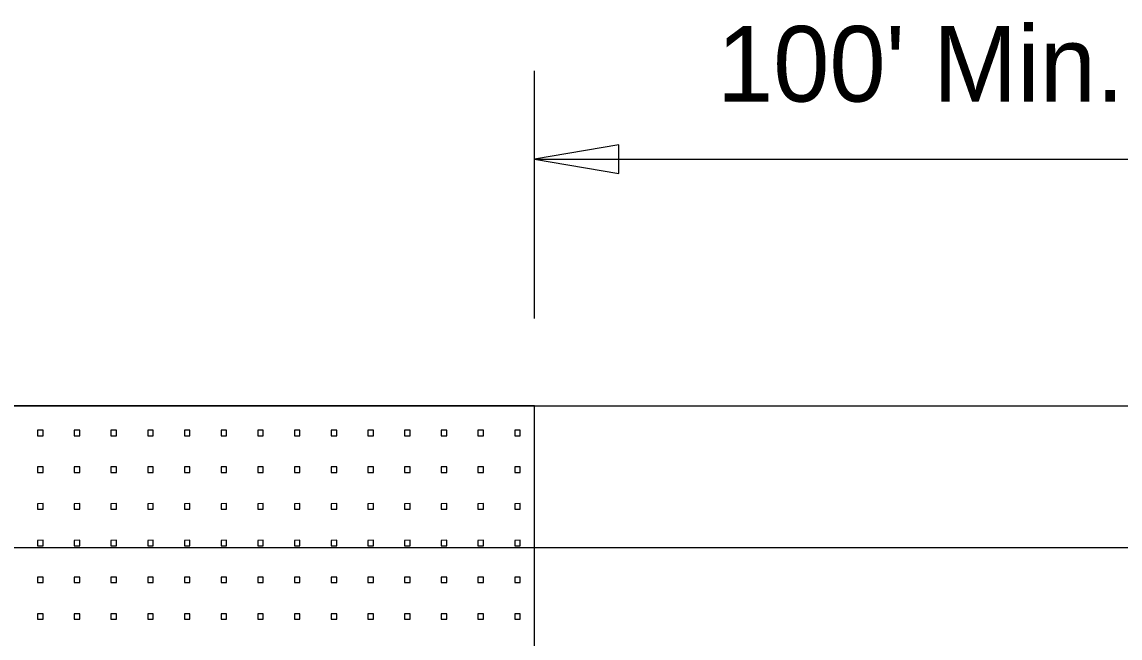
# Model space of a CAD drawing. Extents: x 10000 to 10825, y 10000 to 10530.
# Drawn here: x 10231.1 to 10281.9, y 10433.5 to 10462 of the extents above; entities that cross this region are included whole.
import ezdxf

# ---------------------------------------------------------------- set-up
doc = ezdxf.new("R2010")
doc.units = 0
for name, color, linetype in [('Default', 7, 'Continuous'), ('Dimension', 7, 'Continuous'), ('TextStructures', 7, 'Continuous')]:
    doc.layers.add(name, color=color, linetype=linetype)

msp = doc.modelspace()

# ---------------------------------------------------------------- linework, layer by layer
at = {"layer": 'Default'}
for p, q in [((10254.769, 10448.295), (10254.769, 10459.771)), ((10254.769, 10455.673), (10290.826, 10455.673)), ((10049.563, 10444.263), (10394.364, 10444.263)), ((10254.769, 10444.263), (10187.058, 10444.263)), ((10254.769, 10404.79), (10254.769, 10444.263)), ((10049.563, 10437.701), (10394.364, 10437.701))]:
    msp.add_line(p, q, dxfattribs=at)
for points in [[(10232.033, 10442.872), (10232.033, 10443.128), (10231.778, 10443.127), (10231.778, 10442.872), (10232.033, 10442.872)], [(10232.033, 10442.872), (10232.033, 10443.128), (10231.778, 10443.127), (10231.778, 10442.872), (10232.033, 10442.872)], [(10233.732, 10442.872), (10233.732, 10443.128), (10233.477, 10443.127), (10233.477, 10442.872), (10233.732, 10442.872)], [(10233.732, 10442.872), (10233.732, 10443.128), (10233.477, 10443.127), (10233.477, 10442.872), (10233.732, 10442.872)], [(10235.43, 10442.872), (10235.43, 10443.128), (10235.175, 10443.127), (10235.175, 10442.872), (10235.43, 10442.872)], [(10235.43, 10442.872), (10235.43, 10443.128), (10235.175, 10443.127), (10235.175, 10442.872), (10235.43, 10442.872)], [(10237.128, 10442.872), (10237.128, 10443.128), (10236.874, 10443.127), (10236.874, 10442.872), (10237.128, 10442.872)], [(10237.128, 10442.872), (10237.128, 10443.128), (10236.874, 10443.127), (10236.874, 10442.872), (10237.128, 10442.872)], [(10238.827, 10442.872), (10238.827, 10443.128), (10238.572, 10443.127), (10238.572, 10442.872), (10238.827, 10442.872)], [(10238.827, 10442.872), (10238.827, 10443.128), (10238.572, 10443.127), (10238.572, 10442.872), (10238.827, 10442.872)], [(10240.525, 10442.872), (10240.525, 10443.128), (10240.271, 10443.127), (10240.271, 10442.872), (10240.525, 10442.872)], [(10240.525, 10442.872), (10240.525, 10443.128), (10240.271, 10443.127), (10240.271, 10442.872), (10240.525, 10442.872)], [(10242.224, 10442.872), (10242.224, 10443.128), (10241.969, 10443.127), (10241.969, 10442.872), (10242.224, 10442.872)], [(10242.224, 10442.872), (10242.224, 10443.128), (10241.969, 10443.127), (10241.969, 10442.872), (10242.224, 10442.872)], [(10243.922, 10442.872), (10243.922, 10443.128), (10243.668, 10443.127), (10243.668, 10442.872), (10243.922, 10442.872)], [(10243.922, 10442.872), (10243.922, 10443.128), (10243.668, 10443.127), (10243.668, 10442.872), (10243.922, 10442.872)], [(10245.621, 10442.872), (10245.621, 10443.128), (10245.366, 10443.127), (10245.366, 10442.872), (10245.621, 10442.872)], [(10245.621, 10442.872), (10245.621, 10443.128), (10245.366, 10443.127), (10245.366, 10442.872), (10245.621, 10442.872)], [(10247.319, 10442.872), (10247.319, 10443.128), (10247.065, 10443.127), (10247.065, 10442.872), (10247.319, 10442.872)], [(10247.319, 10442.872), (10247.319, 10443.128), (10247.065, 10443.127), (10247.065, 10442.872), (10247.319, 10442.872)], [(10249.018, 10442.872), (10249.018, 10443.128), (10248.763, 10443.127), (10248.763, 10442.872), (10249.018, 10442.872)], [(10249.018, 10442.872), (10249.018, 10443.128), (10248.763, 10443.127), (10248.763, 10442.872), (10249.018, 10442.872)], [(10250.716, 10442.872), (10250.716, 10443.128), (10250.462, 10443.127), (10250.462, 10442.872), (10250.716, 10442.872)], [(10250.716, 10442.872), (10250.716, 10443.128), (10250.462, 10443.127), (10250.462, 10442.872), (10250.716, 10442.872)], [(10252.415, 10442.872), (10252.415, 10443.128), (10252.16, 10443.127), (10252.16, 10442.872), (10252.415, 10442.872)], [(10252.415, 10442.872), (10252.415, 10443.128), (10252.16, 10443.127), (10252.16, 10442.872), (10252.415, 10442.872)], [(10254.113, 10442.872), (10254.113, 10443.128), (10253.858, 10443.127), (10253.858, 10442.872), (10254.113, 10442.872)], [(10254.113, 10442.872), (10254.113, 10443.128), (10253.858, 10443.127), (10253.858, 10442.872), (10254.113, 10442.872)], [(10232.033, 10441.174), (10232.033, 10441.43), (10231.778, 10441.429), (10231.778, 10441.174), (10232.033, 10441.174)], [(10232.033, 10441.174), (10232.033, 10441.43), (10231.778, 10441.429), (10231.778, 10441.174), (10232.033, 10441.174)], [(10233.732, 10441.174), (10233.732, 10441.43), (10233.477, 10441.429), (10233.477, 10441.174), (10233.732, 10441.174)], [(10233.732, 10441.174), (10233.732, 10441.43), (10233.477, 10441.429), (10233.477, 10441.174), (10233.732, 10441.174)], [(10235.43, 10441.174), (10235.43, 10441.43), (10235.175, 10441.429), (10235.175, 10441.174), (10235.43, 10441.174)], [(10235.43, 10441.174), (10235.43, 10441.43), (10235.175, 10441.429), (10235.175, 10441.174), (10235.43, 10441.174)], [(10237.128, 10441.174), (10237.128, 10441.43), (10236.874, 10441.429), (10236.874, 10441.174), (10237.128, 10441.174)], [(10237.128, 10441.174), (10237.128, 10441.43), (10236.874, 10441.429), (10236.874, 10441.174), (10237.128, 10441.174)], [(10238.827, 10441.174), (10238.827, 10441.43), (10238.572, 10441.429), (10238.572, 10441.174), (10238.827, 10441.174)], [(10238.827, 10441.174), (10238.827, 10441.43), (10238.572, 10441.429), (10238.572, 10441.174), (10238.827, 10441.174)], [(10240.525, 10441.174), (10240.525, 10441.43), (10240.271, 10441.429), (10240.271, 10441.174), (10240.525, 10441.174)], [(10240.525, 10441.174), (10240.525, 10441.43), (10240.271, 10441.429), (10240.271, 10441.174), (10240.525, 10441.174)], [(10242.224, 10441.174), (10242.224, 10441.43), (10241.969, 10441.429), (10241.969, 10441.174), (10242.224, 10441.174)], [(10242.224, 10441.174), (10242.224, 10441.43), (10241.969, 10441.429), (10241.969, 10441.174), (10242.224, 10441.174)], [(10243.922, 10441.174), (10243.922, 10441.43), (10243.668, 10441.429), (10243.668, 10441.174), (10243.922, 10441.174)], [(10243.922, 10441.174), (10243.922, 10441.43), (10243.668, 10441.429), (10243.668, 10441.174), (10243.922, 10441.174)], [(10245.621, 10441.174), (10245.621, 10441.43), (10245.366, 10441.429), (10245.366, 10441.174), (10245.621, 10441.174)], [(10245.621, 10441.174), (10245.621, 10441.43), (10245.366, 10441.429), (10245.366, 10441.174), (10245.621, 10441.174)], [(10247.319, 10441.174), (10247.319, 10441.43), (10247.065, 10441.429), (10247.065, 10441.174), (10247.319, 10441.174)], [(10247.319, 10441.174), (10247.319, 10441.43), (10247.065, 10441.429), (10247.065, 10441.174), (10247.319, 10441.174)], [(10249.018, 10441.174), (10249.018, 10441.43), (10248.763, 10441.429), (10248.763, 10441.174), (10249.018, 10441.174)], [(10249.018, 10441.174), (10249.018, 10441.43), (10248.763, 10441.429), (10248.763, 10441.174), (10249.018, 10441.174)], [(10250.716, 10441.174), (10250.716, 10441.43), (10250.462, 10441.429), (10250.462, 10441.174), (10250.716, 10441.174)], [(10250.716, 10441.174), (10250.716, 10441.43), (10250.462, 10441.429), (10250.462, 10441.174), (10250.716, 10441.174)], [(10252.415, 10441.174), (10252.415, 10441.43), (10252.16, 10441.429), (10252.16, 10441.174), (10252.415, 10441.174)], [(10252.415, 10441.174), (10252.415, 10441.43), (10252.16, 10441.429), (10252.16, 10441.174), (10252.415, 10441.174)], [(10254.113, 10441.174), (10254.113, 10441.43), (10253.858, 10441.429), (10253.858, 10441.174), (10254.113, 10441.174)], [(10254.113, 10441.174), (10254.113, 10441.43), (10253.858, 10441.429), (10253.858, 10441.174), (10254.113, 10441.174)], [(10232.033, 10439.475), (10232.033, 10439.731), (10231.778, 10439.73), (10231.778, 10439.475), (10232.033, 10439.475)], [(10232.033, 10439.475), (10232.033, 10439.731), (10231.778, 10439.73), (10231.778, 10439.475), (10232.033, 10439.475)], [(10233.732, 10439.475), (10233.732, 10439.731), (10233.477, 10439.73), (10233.477, 10439.475), (10233.732, 10439.475)], [(10233.732, 10439.475), (10233.732, 10439.731), (10233.477, 10439.73), (10233.477, 10439.475), (10233.732, 10439.475)], [(10235.43, 10439.475), (10235.43, 10439.731), (10235.175, 10439.73), (10235.175, 10439.475), (10235.43, 10439.475)], [(10235.43, 10439.475), (10235.43, 10439.731), (10235.175, 10439.73), (10235.175, 10439.475), (10235.43, 10439.475)], [(10237.128, 10439.475), (10237.128, 10439.731), (10236.874, 10439.73), (10236.874, 10439.475), (10237.128, 10439.475)], [(10237.128, 10439.475), (10237.128, 10439.731), (10236.874, 10439.73), (10236.874, 10439.475), (10237.128, 10439.475)], [(10238.827, 10439.475), (10238.827, 10439.731), (10238.572, 10439.73), (10238.572, 10439.475), (10238.827, 10439.475)], [(10238.827, 10439.475), (10238.827, 10439.731), (10238.572, 10439.73), (10238.572, 10439.475), (10238.827, 10439.475)], [(10240.525, 10439.475), (10240.525, 10439.731), (10240.271, 10439.73), (10240.271, 10439.475), (10240.525, 10439.475)], [(10240.525, 10439.475), (10240.525, 10439.731), (10240.271, 10439.73), (10240.271, 10439.475), (10240.525, 10439.475)], [(10242.224, 10439.475), (10242.224, 10439.731), (10241.969, 10439.73), (10241.969, 10439.475), (10242.224, 10439.475)], [(10242.224, 10439.475), (10242.224, 10439.731), (10241.969, 10439.73), (10241.969, 10439.475), (10242.224, 10439.475)], [(10243.922, 10439.475), (10243.922, 10439.731), (10243.668, 10439.73), (10243.668, 10439.475), (10243.922, 10439.475)], [(10243.922, 10439.475), (10243.922, 10439.731), (10243.668, 10439.73), (10243.668, 10439.475), (10243.922, 10439.475)], [(10245.621, 10439.475), (10245.621, 10439.731), (10245.366, 10439.73), (10245.366, 10439.475), (10245.621, 10439.475)], [(10245.621, 10439.475), (10245.621, 10439.731), (10245.366, 10439.73), (10245.366, 10439.475), (10245.621, 10439.475)], [(10247.319, 10439.475), (10247.319, 10439.731), (10247.065, 10439.73), (10247.065, 10439.475), (10247.319, 10439.475)], [(10247.319, 10439.475), (10247.319, 10439.731), (10247.065, 10439.73), (10247.065, 10439.475), (10247.319, 10439.475)], [(10249.018, 10439.475), (10249.018, 10439.731), (10248.763, 10439.73), (10248.763, 10439.475), (10249.018, 10439.475)], [(10249.018, 10439.475), (10249.018, 10439.731), (10248.763, 10439.73), (10248.763, 10439.475), (10249.018, 10439.475)], [(10250.716, 10439.475), (10250.716, 10439.731), (10250.462, 10439.73), (10250.462, 10439.475), (10250.716, 10439.475)], [(10250.716, 10439.475), (10250.716, 10439.731), (10250.462, 10439.73), (10250.462, 10439.475), (10250.716, 10439.475)], [(10252.415, 10439.475), (10252.415, 10439.731), (10252.16, 10439.73), (10252.16, 10439.475), (10252.415, 10439.475)], [(10252.415, 10439.475), (10252.415, 10439.731), (10252.16, 10439.73), (10252.16, 10439.475), (10252.415, 10439.475)], [(10254.113, 10439.475), (10254.113, 10439.731), (10253.858, 10439.73), (10253.858, 10439.475), (10254.113, 10439.475)], [(10254.113, 10439.475), (10254.113, 10439.731), (10253.858, 10439.73), (10253.858, 10439.475), (10254.113, 10439.475)], [(10232.033, 10437.777), (10232.033, 10438.033), (10231.778, 10438.032), (10231.778, 10437.777), (10232.033, 10437.777)], [(10232.033, 10437.777), (10232.033, 10438.033), (10231.778, 10438.032), (10231.778, 10437.777), (10232.033, 10437.777)], [(10233.732, 10437.777), (10233.732, 10438.033), (10233.477, 10438.032), (10233.477, 10437.777), (10233.732, 10437.777)], [(10233.732, 10437.777), (10233.732, 10438.033), (10233.477, 10438.032), (10233.477, 10437.777), (10233.732, 10437.777)], [(10235.43, 10437.777), (10235.43, 10438.033), (10235.175, 10438.032), (10235.175, 10437.777), (10235.43, 10437.777)], [(10235.43, 10437.777), (10235.43, 10438.033), (10235.175, 10438.032), (10235.175, 10437.777), (10235.43, 10437.777)], [(10237.128, 10437.777), (10237.128, 10438.033), (10236.874, 10438.032), (10236.874, 10437.777), (10237.128, 10437.777)], [(10237.128, 10437.777), (10237.128, 10438.033), (10236.874, 10438.032), (10236.874, 10437.777), (10237.128, 10437.777)], [(10238.827, 10437.777), (10238.827, 10438.033), (10238.572, 10438.032), (10238.572, 10437.777), (10238.827, 10437.777)], [(10238.827, 10437.777), (10238.827, 10438.033), (10238.572, 10438.032), (10238.572, 10437.777), (10238.827, 10437.777)], [(10240.525, 10437.777), (10240.525, 10438.033), (10240.271, 10438.032), (10240.271, 10437.777), (10240.525, 10437.777)], [(10240.525, 10437.777), (10240.525, 10438.033), (10240.271, 10438.032), (10240.271, 10437.777), (10240.525, 10437.777)], [(10242.224, 10437.777), (10242.224, 10438.033), (10241.969, 10438.032), (10241.969, 10437.777), (10242.224, 10437.777)], [(10242.224, 10437.777), (10242.224, 10438.033), (10241.969, 10438.032), (10241.969, 10437.777), (10242.224, 10437.777)], [(10243.922, 10437.777), (10243.922, 10438.033), (10243.668, 10438.032), (10243.668, 10437.777), (10243.922, 10437.777)], [(10243.922, 10437.777), (10243.922, 10438.033), (10243.668, 10438.032), (10243.668, 10437.777), (10243.922, 10437.777)], [(10245.621, 10437.777), (10245.621, 10438.033), (10245.366, 10438.032), (10245.366, 10437.777), (10245.621, 10437.777)], [(10245.621, 10437.777), (10245.621, 10438.033), (10245.366, 10438.032), (10245.366, 10437.777), (10245.621, 10437.777)], [(10247.319, 10437.777), (10247.319, 10438.033), (10247.065, 10438.032), (10247.065, 10437.777), (10247.319, 10437.777)], [(10247.319, 10437.777), (10247.319, 10438.033), (10247.065, 10438.032), (10247.065, 10437.777), (10247.319, 10437.777)], [(10249.018, 10437.777), (10249.018, 10438.033), (10248.763, 10438.032), (10248.763, 10437.777), (10249.018, 10437.777)], [(10249.018, 10437.777), (10249.018, 10438.033), (10248.763, 10438.032), (10248.763, 10437.777), (10249.018, 10437.777)], [(10250.716, 10437.777), (10250.716, 10438.033), (10250.462, 10438.032), (10250.462, 10437.777), (10250.716, 10437.777)], [(10250.716, 10437.777), (10250.716, 10438.033), (10250.462, 10438.032), (10250.462, 10437.777), (10250.716, 10437.777)], [(10252.415, 10437.777), (10252.415, 10438.033), (10252.16, 10438.032), (10252.16, 10437.777), (10252.415, 10437.777)], [(10252.415, 10437.777), (10252.415, 10438.033), (10252.16, 10438.032), (10252.16, 10437.777), (10252.415, 10437.777)], [(10254.113, 10437.777), (10254.113, 10438.033), (10253.858, 10438.032), (10253.858, 10437.777), (10254.113, 10437.777)], [(10254.113, 10437.777), (10254.113, 10438.033), (10253.858, 10438.032), (10253.858, 10437.777), (10254.113, 10437.777)], [(10232.033, 10436.078), (10232.033, 10436.334), (10231.778, 10436.333), (10231.778, 10436.078), (10232.033, 10436.078)], [(10232.033, 10436.078), (10232.033, 10436.334), (10231.778, 10436.333), (10231.778, 10436.078), (10232.033, 10436.078)], [(10233.732, 10436.078), (10233.732, 10436.334), (10233.477, 10436.333), (10233.477, 10436.078), (10233.732, 10436.078)], [(10233.732, 10436.078), (10233.732, 10436.334), (10233.477, 10436.333), (10233.477, 10436.078), (10233.732, 10436.078)], [(10235.43, 10436.078), (10235.43, 10436.334), (10235.175, 10436.333), (10235.175, 10436.078), (10235.43, 10436.078)], [(10235.43, 10436.078), (10235.43, 10436.334), (10235.175, 10436.333), (10235.175, 10436.078), (10235.43, 10436.078)], [(10237.128, 10436.078), (10237.128, 10436.334), (10236.874, 10436.333), (10236.874, 10436.078), (10237.128, 10436.078)], [(10237.128, 10436.078), (10237.128, 10436.334), (10236.874, 10436.333), (10236.874, 10436.078), (10237.128, 10436.078)], [(10238.827, 10436.078), (10238.827, 10436.334), (10238.572, 10436.333), (10238.572, 10436.078), (10238.827, 10436.078)], [(10238.827, 10436.078), (10238.827, 10436.334), (10238.572, 10436.333), (10238.572, 10436.078), (10238.827, 10436.078)], [(10240.525, 10436.078), (10240.525, 10436.334), (10240.271, 10436.333), (10240.271, 10436.078), (10240.525, 10436.078)], [(10240.525, 10436.078), (10240.525, 10436.334), (10240.271, 10436.333), (10240.271, 10436.078), (10240.525, 10436.078)], [(10242.224, 10436.078), (10242.224, 10436.334), (10241.969, 10436.333), (10241.969, 10436.078), (10242.224, 10436.078)], [(10242.224, 10436.078), (10242.224, 10436.334), (10241.969, 10436.333), (10241.969, 10436.078), (10242.224, 10436.078)], [(10243.922, 10436.078), (10243.922, 10436.334), (10243.668, 10436.333), (10243.668, 10436.078), (10243.922, 10436.078)], [(10243.922, 10436.078), (10243.922, 10436.334), (10243.668, 10436.333), (10243.668, 10436.078), (10243.922, 10436.078)], [(10245.621, 10436.078), (10245.621, 10436.334), (10245.366, 10436.333), (10245.366, 10436.078), (10245.621, 10436.078)], [(10245.621, 10436.078), (10245.621, 10436.334), (10245.366, 10436.333), (10245.366, 10436.078), (10245.621, 10436.078)], [(10247.319, 10436.078), (10247.319, 10436.334), (10247.065, 10436.333), (10247.065, 10436.078), (10247.319, 10436.078)], [(10247.319, 10436.078), (10247.319, 10436.334), (10247.065, 10436.333), (10247.065, 10436.078), (10247.319, 10436.078)], [(10249.018, 10436.078), (10249.018, 10436.334), (10248.763, 10436.333), (10248.763, 10436.078), (10249.018, 10436.078)], [(10249.018, 10436.078), (10249.018, 10436.334), (10248.763, 10436.333), (10248.763, 10436.078), (10249.018, 10436.078)], [(10250.716, 10436.078), (10250.716, 10436.334), (10250.462, 10436.333), (10250.462, 10436.078), (10250.716, 10436.078)], [(10250.716, 10436.078), (10250.716, 10436.334), (10250.462, 10436.333), (10250.462, 10436.078), (10250.716, 10436.078)], [(10252.415, 10436.078), (10252.415, 10436.334), (10252.16, 10436.333), (10252.16, 10436.078), (10252.415, 10436.078)], [(10252.415, 10436.078), (10252.415, 10436.334), (10252.16, 10436.333), (10252.16, 10436.078), (10252.415, 10436.078)], [(10254.113, 10436.078), (10254.113, 10436.334), (10253.858, 10436.333), (10253.858, 10436.078), (10254.113, 10436.078)], [(10254.113, 10436.078), (10254.113, 10436.334), (10253.858, 10436.333), (10253.858, 10436.078), (10254.113, 10436.078)], [(10232.033, 10434.38), (10232.033, 10434.636), (10231.778, 10434.635), (10231.778, 10434.38), (10232.033, 10434.38)], [(10232.033, 10434.38), (10232.033, 10434.636), (10231.778, 10434.635), (10231.778, 10434.38), (10232.033, 10434.38)], [(10233.732, 10434.38), (10233.732, 10434.636), (10233.477, 10434.635), (10233.477, 10434.38), (10233.732, 10434.38)], [(10233.732, 10434.38), (10233.732, 10434.636), (10233.477, 10434.635), (10233.477, 10434.38), (10233.732, 10434.38)], [(10235.43, 10434.38), (10235.43, 10434.636), (10235.175, 10434.635), (10235.175, 10434.38), (10235.43, 10434.38)], [(10235.43, 10434.38), (10235.43, 10434.636), (10235.175, 10434.635), (10235.175, 10434.38), (10235.43, 10434.38)], [(10237.128, 10434.38), (10237.128, 10434.636), (10236.874, 10434.635), (10236.874, 10434.38), (10237.128, 10434.38)], [(10237.128, 10434.38), (10237.128, 10434.636), (10236.874, 10434.635), (10236.874, 10434.38), (10237.128, 10434.38)], [(10238.827, 10434.38), (10238.827, 10434.636), (10238.572, 10434.635), (10238.572, 10434.38), (10238.827, 10434.38)], [(10238.827, 10434.38), (10238.827, 10434.636), (10238.572, 10434.635), (10238.572, 10434.38), (10238.827, 10434.38)], [(10240.525, 10434.38), (10240.525, 10434.636), (10240.271, 10434.635), (10240.271, 10434.38), (10240.525, 10434.38)], [(10240.525, 10434.38), (10240.525, 10434.636), (10240.271, 10434.635), (10240.271, 10434.38), (10240.525, 10434.38)], [(10242.224, 10434.38), (10242.224, 10434.636), (10241.969, 10434.635), (10241.969, 10434.38), (10242.224, 10434.38)], [(10242.224, 10434.38), (10242.224, 10434.636), (10241.969, 10434.635), (10241.969, 10434.38), (10242.224, 10434.38)], [(10243.922, 10434.38), (10243.922, 10434.636), (10243.668, 10434.635), (10243.668, 10434.38), (10243.922, 10434.38)], [(10243.922, 10434.38), (10243.922, 10434.636), (10243.668, 10434.635), (10243.668, 10434.38), (10243.922, 10434.38)], [(10245.621, 10434.38), (10245.621, 10434.636), (10245.366, 10434.635), (10245.366, 10434.38), (10245.621, 10434.38)], [(10245.621, 10434.38), (10245.621, 10434.636), (10245.366, 10434.635), (10245.366, 10434.38), (10245.621, 10434.38)], [(10247.319, 10434.38), (10247.319, 10434.636), (10247.065, 10434.635), (10247.065, 10434.38), (10247.319, 10434.38)], [(10247.319, 10434.38), (10247.319, 10434.636), (10247.065, 10434.635), (10247.065, 10434.38), (10247.319, 10434.38)], [(10249.018, 10434.38), (10249.018, 10434.636), (10248.763, 10434.635), (10248.763, 10434.38), (10249.018, 10434.38)], [(10249.018, 10434.38), (10249.018, 10434.636), (10248.763, 10434.635), (10248.763, 10434.38), (10249.018, 10434.38)], [(10250.716, 10434.38), (10250.716, 10434.636), (10250.462, 10434.635), (10250.462, 10434.38), (10250.716, 10434.38)], [(10250.716, 10434.38), (10250.716, 10434.636), (10250.462, 10434.635), (10250.462, 10434.38), (10250.716, 10434.38)], [(10252.415, 10434.38), (10252.415, 10434.636), (10252.16, 10434.635), (10252.16, 10434.38), (10252.415, 10434.38)], [(10252.415, 10434.38), (10252.415, 10434.636), (10252.16, 10434.635), (10252.16, 10434.38), (10252.415, 10434.38)], [(10254.113, 10434.38), (10254.113, 10434.636), (10253.858, 10434.635), (10253.858, 10434.38), (10254.113, 10434.38)], [(10254.113, 10434.38), (10254.113, 10434.636), (10253.858, 10434.635), (10253.858, 10434.38), (10254.113, 10434.38)]]:
    msp.add_lwpolyline(points, dxfattribs=at)
at = {"layer": 'Dimension'}
msp.add_lwpolyline([(10254.769, 10455.673), (10258.674, 10455.012), (10258.674, 10456.335)], close=True, dxfattribs=at)

# ---------------------------------------------------------------- texts
at = {"layer": 'TextStructures'}
msp.add_text("100' Min.", height=3.5, rotation=0.0007, dxfattribs=at).set_placement((10263.218, 10458.342))

doc.saveas('drawing.dxf')
